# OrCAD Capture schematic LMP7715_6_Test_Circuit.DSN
size A; title: Single and Dual Precision, 17 MHz, Low Noise, CMOS; rev: 1.1; note: Datasheet: SNOSAV0E EVM: N/A
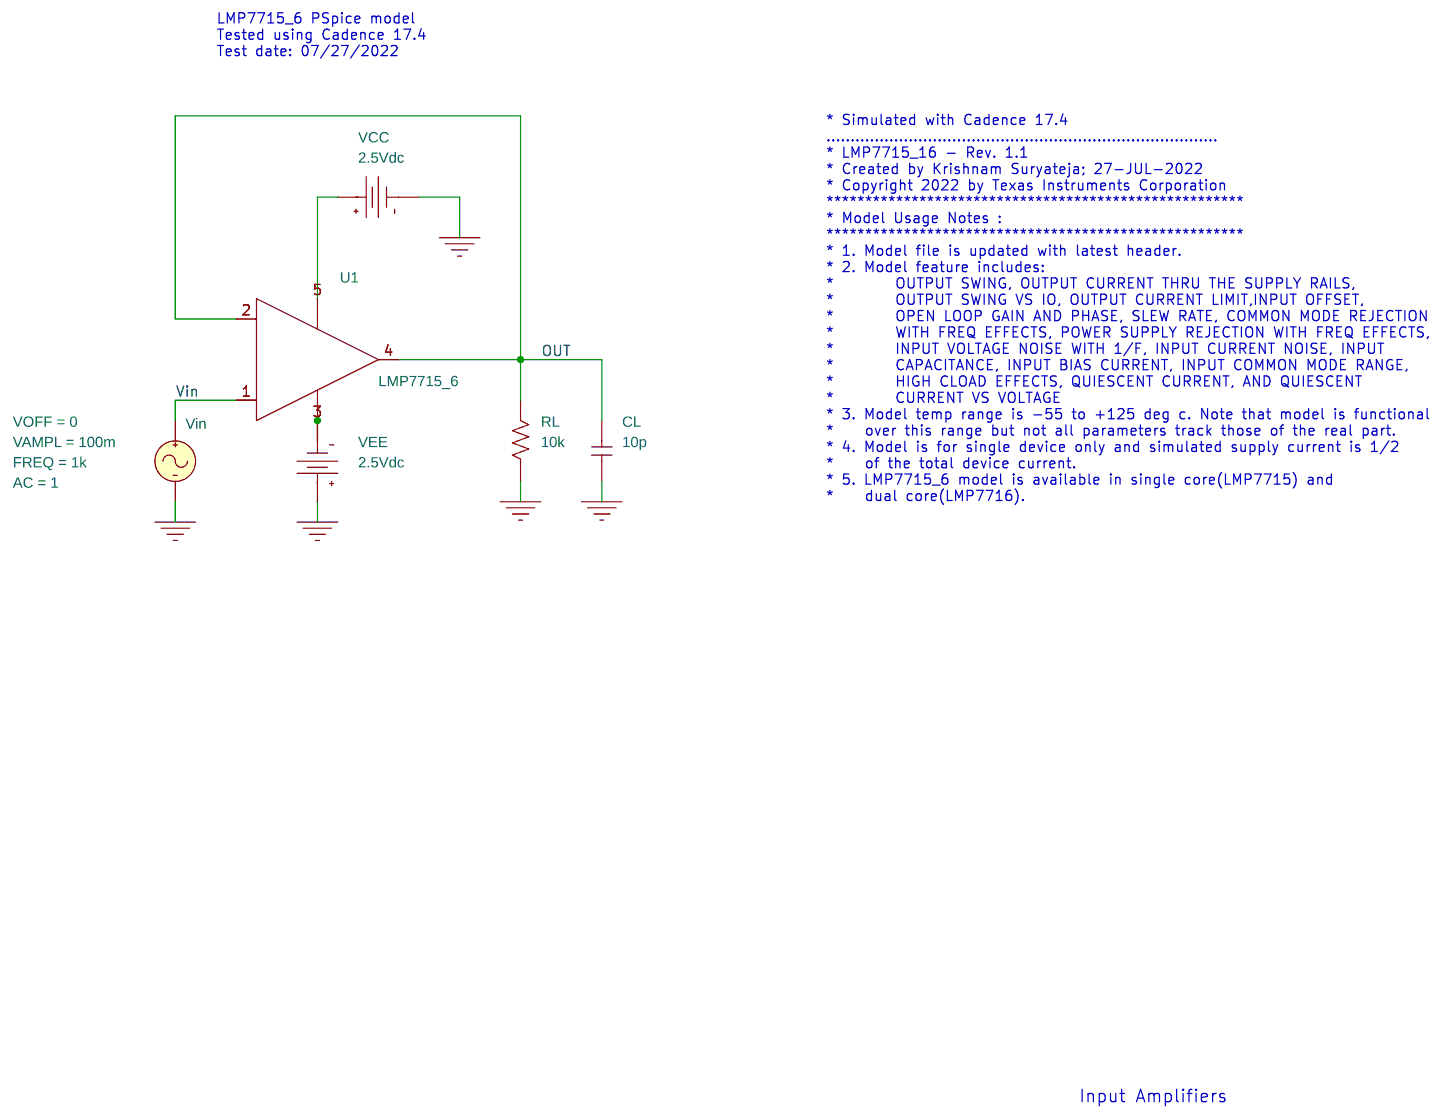
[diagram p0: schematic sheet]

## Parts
CL  10p  [RAD/CK05]
RL  10k  [AX/RC05]
U1  LMP7715_6
VCC  VDC
VEE  VDC
Vin  VSIN

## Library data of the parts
CL = C
RL = R
U1 = LMP7715_6
VCC VEE = VDC: DC: 2.5Vdc
Vin = VSIN: AC: 1; FREQ: 1k; VAMPL: 100m; VOFF: 0

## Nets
Vin: U1.1(+) Vin.1(+)
0: CL.1 RL.1 VCC.1(-) VEE.0(+) Vin.2(-)
OUT: CL.2 RL.2 U1.2(-) U1.4(OUT)
N22995: U1.5(V+) VCC.0(+)
N23017: U1.3(V-) VEE.1(-)

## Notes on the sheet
- LMP7715_6 PSpice model
  Tested using Cadence 17.4
  Test date: 07/27/2022
- * Simulated with Cadence 17.4
  .................................................................................
  * LMP7715_16 - Rev. 1.1
  * Created by Krishnam Suryateja; 27-JUL-2022
  * Copyright 2022 by Texas Instruments Corporation
  ******************************************************
  * Model Usage Notes :
  ******************************************************
  * 1. Model file is updated with latest header.
  * 2. Model feature includes:
  *	    OUTPUT SWING, OUTPUT CURRENT THRU THE SUPPLY RAILS,
  *	    OUTPUT SWING VS IO, OUTPUT CURRENT LIMIT,INPUT OFFSET,
  *	    OPEN LOOP GAIN AND PHASE, SLEW RATE, COMMON MODE REJECTION
  *	    WITH FREQ EFFECTS, POWER SUPPLY REJECTION WITH FREQ EFFECTS,
  *	    INPUT VOLTAGE NOISE WITH 1/F, INPUT CURRENT NOISE, INPUT
  *	    CAPACITANCE, INPUT BIAS CURRENT, INPUT COMMON MODE RANGE,
  *	    HIGH CLOAD EFFECTS, QUIESCENT CURRENT, AND QUIESCENT
  *	    CURRENT VS VOLTAGE
  * 3. Model temp range is -55 to +125 deg c. Note that model is functional
  *    over this range but not all parameters track those of the real part.
  * 4. Model is for single device only and simulated supply current is 1/2
  *    of the total device current.
  * 5. LMP7715_6 model is available in single core(LMP7715) and
  *    dual core(LMP7716).
- Input Amplifiers
